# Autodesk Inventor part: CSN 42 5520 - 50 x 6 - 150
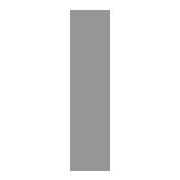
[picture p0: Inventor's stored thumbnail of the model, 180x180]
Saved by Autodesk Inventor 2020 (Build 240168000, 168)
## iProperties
Created: 2019-01
Part Number: CSN 42 5520 - 50 x 6 - 150
Material: Ocel
Description: Tyč
Document SubType Name: Modeling
Standard: CSN 42 5520
Designer: doma
Standards Organization: CSN
Language: cs-CZ
Size Designation: 50 x 6 - 150
Categories: <MemberInstance><Categories><Category DisplayName="Konstrukční profily" InternalName="089c4875-fa83-4c05-b084-43b9cc11f5ed" Mnemonic="GRDR"><CategoryParameter D
Stock Number: 50 x 6
Density: 7.85 g/cm^3
Appearance: Plech
Mass: 353.25 g
Surface Area: 174 cm^2
Volume: 45 cm^3
IsCustomPart: 1
G_L: 150,000 mm
Author: doma
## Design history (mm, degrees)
node "Počáteční rovina"
node "Koncová rovina"
sketch "Náčrt"
  geometry: L1 (3, -25)-(-3, -25); L2 (-3, -25)-(-3, 25); L3 (-3, 25)-(3, 25); L4 (3, 25)-(3, -25); L5 (-6, 0)-(8, 0); L6 (0, -30)-(0, 40); L7 (0, 54)-(0, -44) reference; L8 (-9.2, 0)-(13.2, 0) reference
  constraints: 12 end point, 2 collinear, 2 parallel, 1 horizontal, 1 perpendicular
  dimensions: "d0" = 50 distance between parallel lines of L3 L1 (= G_W); "d1" = 6 distance between parallel lines of L4 L2 (= G_H); "d4" = 3 distance between parallel lines of L6 L4 (= 0.5 x d1); "d5" = 25 distance between parallel lines of L5 L3 (= 0.5 x d0)
extrude "Těleso" new body sketch "Náčrt" stored distance "d2" = 150 (= G_L); taper "d3" = 0 deg
node "Driven Length"
  sketch "Sketch3"
    geometry: L1 (0, 0)-(10, 0) reference
    constraints: 2 end point, 1 horizontal
  workplane "Work Plane3"
  sketch "Sketch4"
    geometry: L1 (-2, 0)-(12, 0) reference; L2 (-2, 150)-(12, 150) reference
    dimensions: "d9" = 150 distance between parallel lines of L1 L2 (derived)
body "Solid1"
other parameters: "G_W" = 50 [user parameter; used in 1 equation term], "G_H" = 6 [user parameter; used in 1 equation term], "G_L" = 150 (= d9) [user parameter; used in 1 equation term], "G_OFFSET_START" = 0 [user parameter; used in 1 equation term], "G_OFFSET_END" = 0 [user parameter; used in 1 equation term], "d6" = 0 (computed from G_OFFSET_START), "d8" = 90 deg
